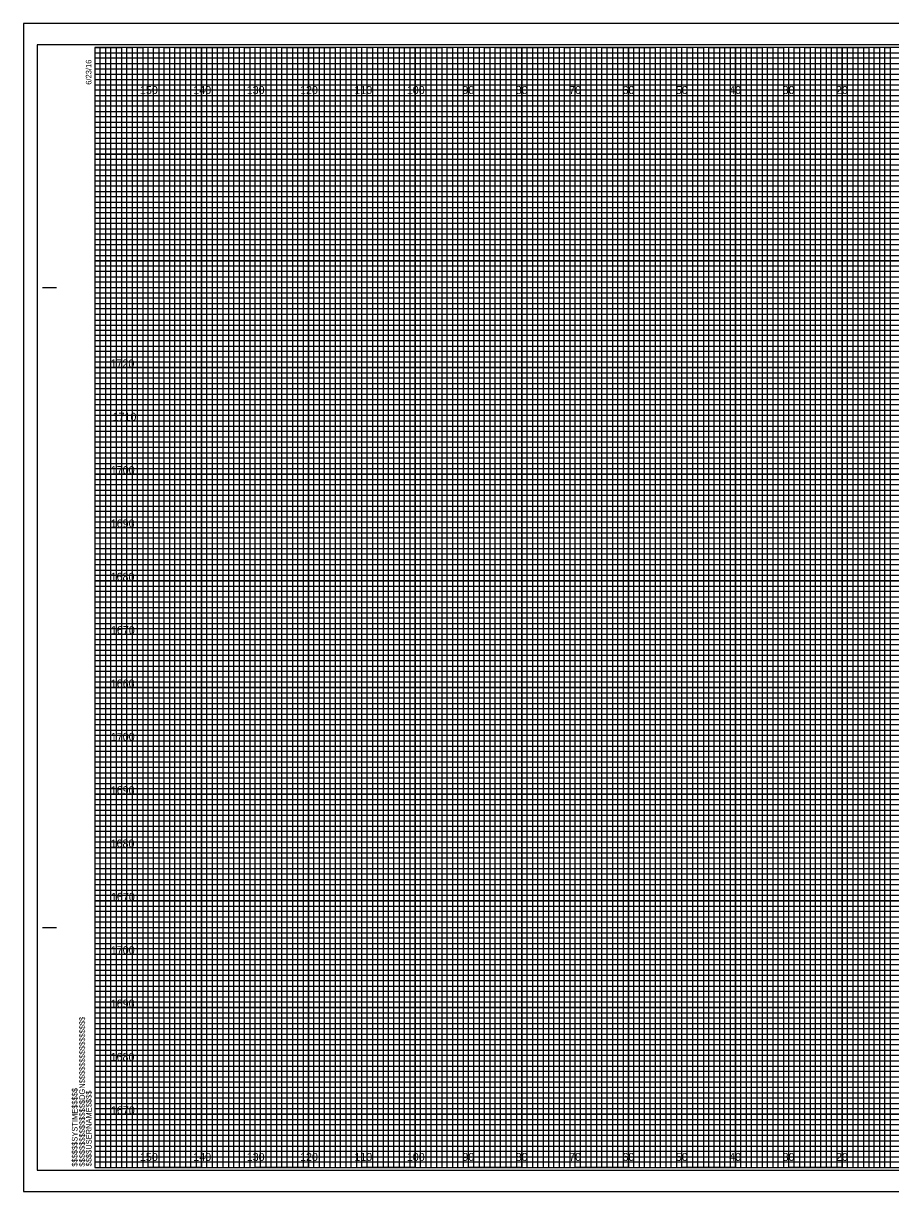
# Model space of a CAD drawing. Extents: x 1443 to 2205, y -29 to 5484.
# Drawn here: x 1443.3 to 1605.8, y -14.8 to 204.2 of the extents above; entities that cross this region are included whole.
import ezdxf

# ---------------------------------------------------------------- set-up
doc = ezdxf.new("R2010")
doc.units = 0
for name, color, linetype in [('Pattern 3', 7, 'Continuous'), ('Prop Retaining Wall', 7, 'Continuous'), ('Prop XS DDE Earthwork Shape', 7, 'Continuous'), ('Prop XS DDE Slope Text', 7, 'Continuous'), ('Prop XS DDE Text', 7, 'Continuous'), ('Prop XS Earthwork Shape', 7, 'Continuous'), ('Prop XS Retaining Wall', 7, 'Continuous'), ('Prop XS Station Labels', 7, 'Continuous'), ('Prop XS Temporary Shoring', 7, 'Continuous'), ('Raster_Level_0', 7, 'Continuous'), ('Scratch_Level_3', 7, 'Continuous')]:
    doc.layers.add(name, color=color, linetype=linetype)

msp = doc.modelspace()

# ---------------------------------------------------------------- linework, layer by layer
at = {"layer": 'Pattern 3'}
for p, q in [((1779.98, 204.21), (1443.28, 204.21)), ((1443.28, 204.21), (1443.28, -14.79)), ((1443.28, -14.79), (1779.98, -14.79))]:
    msp.add_line(p, q, dxfattribs=at)
at = {"layer": 'Prop Retaining Wall'}
for p, q in [((1456.68, 198.71), (1716.68, 198.71)), ((1716.68, 197.69), (1456.68, 197.69)), ((1456.68, 197.69), (1456.68, 196.71)), ((1456.68, 196.71), (1716.68, 196.71)), ((1716.68, 195.6), (1456.68, 195.6)), ((1456.68, 195.6), (1456.68, 193.71)), ((1456.68, 193.71), (1776.68, 193.71))]:
    msp.add_line(p, q, dxfattribs=at)
for points in [[(1456.68, 192.71), (1726.68, 192.71), (1776.68, 192.71), (1776.68, 191.71), (1456.68, 191.71)], [(1456.68, 190.71), (1776.68, 190.71), (1776.68, 188.71), (1456.68, 188.71)], [(1456.68, 187.71), (1776.68, 187.71), (1776.68, 186.71), (1456.68, 186.69)], [(1456.68, 185.71), (1776.68, 185.71), (1776.68, 183.71), (1456.68, 183.71)], [(1456.68, 182.71), (1776.68, 182.71), (1776.68, 181.71), (1456.68, 181.71)], [(1456.68, 180.71), (1776.68, 180.71), (1776.68, 178.71), (1456.68, 178.71)], [(1456.68, 177.71), (1776.68, 177.71), (1776.68, 176.71), (1456.68, 176.71)], [(1456.68, 175.71), (1776.68, 175.71), (1776.68, 173.71), (1456.68, 173.71)], [(1456.68, 172.71), (1776.68, 172.71), (1776.68, 171.71), (1456.68, 171.71)], [(1456.68, 170.71), (1776.68, 170.71), (1776.68, 168.71), (1456.68, 168.71)], [(1456.68, 167.71), (1776.68, 167.71), (1776.68, 166.71), (1456.68, 166.71)], [(1456.68, 165.71), (1776.68, 165.71), (1776.68, 163.66), (1776.68, 162.71), (1776.68, 161.71), (1456.68, 161.71)], [(1456.68, 163.71), (1776.68, 163.71), (1776.68, 162.71), (1456.68, 162.71)], [(1456.68, 160.71), (1776.68, 160.71), (1776.68, 158.71), (1456.68, 158.74)], [(1456.68, 158.74), (1776.68, 158.71), (1776.68, 157.71), (1456.68, 157.71)], [(1456.68, 156.71), (1776.68, 156.71), (1776.68, 155.71), (1456.68, 155.71)], [(1456.68, 153.71), (1776.68, 153.71), (1776.68, 152.71), (1456.68, 152.71)], [(1456.68, 151.71), (1776.68, 151.71), (1776.68, 150.71), (1456.68, 150.71)], [(1456.61, 148.6), (1776.68, 148.6), (1776.68, 147.59), (1456.61, 147.59)], [(1456.68, 146.71), (1776.68, 146.71), (1776.68, 145.71), (1456.68, 145.71)], [(1456.68, 143.71), (1776.68, 143.71), (1776.68, 142.71), (1456.68, 142.71)], [(1456.68, 141.71), (1776.68, 141.71), (1776.68, 140.71), (1456.68, 140.71)], [(1456.68, 138.71), (1776.68, 138.71), (1776.68, 137.71), (1456.68, 137.71)], [(1456.68, 136.71), (1776.68, 136.71), (1776.68, 135.71), (1456.68, 135.71)], [(1456.68, 133.71), (1776.68, 133.71), (1776.68, 132.71), (1456.68, 132.71)], [(1456.68, 131.71), (1776.68, 131.71), (1776.68, 130.71), (1456.68, 130.71)], [(1456.68, 128.71), (1776.68, 128.71), (1776.67, 127.69), (1456.68, 127.71)], [(1456.68, 126.71), (1776.68, 126.71), (1776.68, 125.71), (1456.68, 125.71)], [(1456.68, 123.71), (1776.68, 123.71), (1776.68, 122.71), (1456.68, 122.71)], [(1456.68, 121.71), (1776.68, 121.71), (1776.68, 120.71), (1456.68, 120.71)], [(1456.68, 118.71), (1776.68, 118.71), (1776.68, 117.71), (1456.68, 117.71)], [(1456.68, 116.71), (1776.68, 116.71), (1776.68, 115.71), (1456.68, 115.71)], [(1456.68, 113.71), (1776.68, 113.71), (1776.68, 112.71), (1456.68, 112.71)], [(1456.68, 111.71), (1776.68, 111.71), (1776.68, 110.71), (1456.68, 110.71)], [(1456.68, 108.71), (1776.68, 108.71), (1776.68, 107.71), (1456.68, 107.71)], [(1456.68, 106.7), (1776.75, 106.62), (1776.68, 105.71), (1456.68, 105.71)], [(1456.68, 103.71), (1776.68, 103.71), (1776.68, 102.71), (1456.68, 102.71)], [(1456.68, 101.71), (1776.68, 101.71), (1776.68, 100.71), (1456.68, 100.71)], [(1456.68, 98.71), (1776.68, 98.71), (1776.68, 97.71), (1456.68, 97.71)], [(1456.68, 96.71), (1776.68, 96.71), (1776.68, 95.71), (1456.68, 95.71)], [(1456.68, 93.71), (1776.68, 93.71), (1776.68, 92.71), (1456.68, 92.71)], [(1456.68, 91.71), (1776.68, 91.71), (1776.68, 90.71), (1456.68, 90.71)], [(1456.68, 88.71), (1776.68, 88.71), (1776.68, 87.71), (1456.68, 87.71)], [(1456.68, 86.71), (1776.68, 86.71), (1776.68, 85.71), (1456.68, 85.71)], [(1456.68, 83.71), (1776.68, 83.71), (1776.68, 82.71), (1456.68, 82.71)], [(1456.68, 81.71), (1776.68, 81.71), (1776.68, 80.71), (1456.68, 80.71)], [(1456.68, 78.71), (1776.68, 78.71), (1776.68, 77.71), (1456.68, 77.71)], [(1456.68, 76.71), (1776.68, 76.71), (1776.68, 75.71), (1456.68, 75.71)], [(1456.68, 73.71), (1776.68, 73.71), (1776.68, 72.71), (1456.68, 72.71)], [(1456.68, 71.71), (1776.68, 71.71), (1776.68, 70.71), (1456.68, 70.71)], [(1456.68, 68.71), (1776.68, 68.71), (1776.67, 67.69), (1456.68, 67.71)], [(1456.68, 66.71), (1776.68, 66.71), (1776.68, 65.71), (1456.68, 65.71)], [(1456.68, 63.71), (1776.68, 63.71), (1776.68, 62.71), (1456.68, 62.71)], [(1456.68, 61.71), (1776.68, 61.71), (1776.68, 60.71), (1456.68, 60.71)], [(1456.68, 58.71), (1776.68, 58.71), (1776.68, 57.71), (1456.68, 57.71)], [(1456.68, 56.71), (1776.68, 56.71), (1776.68, 55.71), (1456.68, 55.71)], [(1456.68, 53.71), (1776.68, 53.71), (1776.68, 52.71), (1456.68, 52.71)], [(1456.68, 51.71), (1776.68, 51.71), (1776.68, 50.71), (1456.68, 50.71)], [(1456.68, 48.71), (1776.68, 48.71), (1776.68, 47.71), (1456.68, 47.71)], [(1456.68, 46.7), (1776.75, 46.62), (1776.68, 45.71), (1456.68, 45.71)], [(1456.68, 43.71), (1776.68, 43.71), (1776.68, 42.71), (1456.68, 42.71)], [(1456.68, 41.71), (1776.68, 41.71), (1776.68, 40.71), (1456.68, 40.71)], [(1456.68, 38.71), (1776.68, 38.71), (1776.68, 37.71), (1456.68, 37.71)], [(1456.68, 36.71), (1776.68, 36.71), (1776.68, 35.71), (1456.68, 35.71)], [(1456.68, 33.71), (1776.68, 33.71), (1776.68, 32.71), (1456.68, 32.71)], [(1456.68, 31.71), (1776.68, 31.71), (1776.68, 30.71), (1456.68, 30.71)], [(1456.68, 28.71), (1776.68, 28.71), (1776.68, 27.71), (1456.68, 27.71)], [(1456.68, 26.71), (1776.68, 26.71), (1776.68, 25.71), (1456.68, 25.71)], [(1456.68, 23.71), (1776.68, 23.71), (1776.68, 22.71), (1456.68, 22.71)], [(1456.68, 21.71), (1776.68, 21.71), (1776.68, 20.71), (1456.68, 20.71)], [(1456.68, 18.71), (1776.68, 18.71), (1776.68, 17.71), (1456.68, 17.71)], [(1456.68, 16.71), (1776.68, 16.71), (1776.68, 15.71), (1456.68, 15.71)], [(1456.68, 13.71), (1776.68, 13.71), (1776.68, 12.71), (1456.68, 12.71)], [(1456.68, 11.71), (1776.68, 11.71), (1776.68, 10.71), (1456.68, 10.71)], [(1456.68, 8.71), (1776.68, 8.71), (1776.68, 7.71), (1456.68, 7.71)], [(1456.68, 6.71), (1776.68, 6.71), (1776.68, 5.71), (1456.68, 5.71)], [(1456.68, 3.71), (1776.68, 3.71), (1776.68, 2.71), (1456.68, 2.71)], [(1456.68, 1.71), (1776.68, 1.71), (1776.68, 0.71), (1456.68, 0.71)], [(1456.68, -1.29), (1776.68, -1.29), (1776.68, -2.29), (1456.68, -2.29)], [(1456.68, -3.29), (1776.68, -3.29), (1776.68, -4.29), (1456.68, -4.29)], [(1456.68, -6.29), (1776.68, -6.29), (1776.68, -7.29), (1456.68, -7.29)], [(1456.68, -8.29), (1776.68, -8.29), (1776.68, -9.29), (1456.68, -9.29)]]:
    msp.add_lwpolyline(points, dxfattribs=at)
at = {"layer": 'Prop XS DDE Earthwork Shape'}
msp.add_lwpolyline([(1445.88, -10.79), (1779.08, -10.79), (1779.08, 200.21), (1445.88, 200.21)], close=True, dxfattribs=at)
at = {"layer": 'Prop XS DDE Slope Text'}
for points in [[(1456.68, -10.29), (1457.68, -10.29), (1457.68, 199.71), (1458.68, 199.71), (1458.68, -10.29)], [(1458.68, -10.29), (1459.68, -10.29), (1459.68, 199.71), (1460.68, 199.71), (1460.68, -10.29)], [(1461.68, -10.29), (1462.68, -10.29), (1462.68, 199.71), (1463.68, 199.71), (1463.68, -10.29)], [(1463.68, -10.29), (1464.68, -10.29), (1464.68, 199.71), (1465.68, 199.71), (1465.68, -10.29)], [(1466.68, -10.29), (1467.68, -10.29), (1467.68, 199.71), (1468.68, 199.71), (1468.68, -10.29)], [(1468.68, -10.29), (1469.68, -10.29), (1469.68, 199.71), (1470.68, 199.71), (1470.68, -10.29)], [(1471.68, -10.29), (1472.68, -10.29), (1472.68, 199.71), (1473.68, 199.71), (1473.68, -10.29)], [(1473.68, -10.29), (1474.68, -10.29), (1474.68, 199.71), (1475.68, 199.71), (1475.68, -10.29)], [(1476.68, -10.29), (1477.68, -10.29), (1477.68, 199.71), (1478.68, 199.71), (1478.68, -10.29)], [(1478.68, -10.29), (1479.68, -10.29), (1479.68, 199.71), (1480.68, 199.71), (1480.68, -10.29)], [(1481.68, -10.29), (1482.68, -10.29), (1482.68, 199.71), (1483.68, 199.71), (1483.68, -10.29)], [(1483.68, -10.29), (1484.68, -10.29), (1484.68, 199.71), (1485.68, 199.71), (1485.68, -10.29)], [(1486.68, -10.29), (1487.68, -10.29), (1487.68, 199.71), (1488.68, 199.71), (1488.68, -10.29)], [(1488.68, -10.29), (1489.68, -10.29), (1489.68, 199.71), (1490.68, 199.71), (1490.68, -10.29)], [(1491.68, -10.29), (1492.68, -10.29), (1492.68, 199.71), (1493.68, 199.71), (1493.68, -10.29)], [(1493.68, -10.29), (1494.68, -10.29), (1494.68, 199.71), (1495.68, 199.71), (1495.68, -10.29)], [(1496.68, -10.29), (1497.68, -10.29), (1497.68, 199.71), (1498.68, 199.71), (1498.68, -10.29)], [(1498.68, -10.29), (1499.68, -10.29), (1499.68, 199.71), (1500.68, 199.71), (1500.68, -10.29)], [(1501.68, -10.29), (1502.68, -10.29), (1502.68, 199.71), (1503.68, 199.71), (1503.68, -10.29)], [(1503.68, -10.29), (1504.68, -10.29), (1504.68, 199.71), (1505.68, 199.71), (1505.68, -10.29)], [(1506.68, -10.29), (1507.68, -10.29), (1507.68, 199.71), (1508.68, 199.71), (1508.68, -10.29)], [(1508.68, -10.29), (1509.68, -10.29), (1509.68, 199.71), (1510.68, 199.71), (1510.68, -10.29)], [(1511.68, -10.29), (1512.68, -10.29), (1512.68, 199.71), (1513.68, 199.71), (1513.68, -10.29)], [(1513.68, -10.29), (1514.68, -10.29), (1514.68, 199.71), (1515.68, 199.71), (1515.68, -10.29)], [(1516.68, -10.29), (1517.68, -10.29), (1517.68, 199.71), (1518.68, 199.71), (1518.68, -10.29)], [(1518.68, -10.29), (1519.68, -10.29), (1519.68, 199.71), (1520.68, 199.71), (1520.68, -10.29)], [(1521.68, -10.29), (1522.68, -10.29), (1522.68, 199.71), (1523.68, 199.71), (1523.68, -10.29)], [(1523.68, -10.29), (1524.68, -10.29), (1524.68, 199.71), (1525.68, 199.71), (1525.68, -10.29)], [(1526.68, -10.29), (1527.68, -10.29), (1527.68, 199.71), (1528.68, 199.71), (1528.68, -10.29)], [(1528.68, -10.29), (1529.68, -10.29), (1529.68, 199.71), (1530.68, 199.71), (1530.68, -10.29)], [(1531.68, -10.29), (1532.68, -10.29), (1532.68, 199.71), (1533.68, 199.71), (1533.68, -10.29)], [(1533.68, -10.29), (1534.68, -10.29), (1534.68, 199.71), (1535.68, 199.71), (1535.68, -10.29)], [(1536.68, -10.29), (1537.68, -10.29), (1537.68, 199.71), (1538.68, 199.71), (1538.68, -10.29)], [(1538.68, -10.29), (1539.68, -10.29), (1539.68, 199.71), (1540.68, 199.71), (1540.68, -10.29)], [(1541.68, -10.29), (1542.68, -10.29), (1542.68, 199.71), (1543.68, 199.71), (1543.68, -10.29)], [(1543.68, -10.29), (1544.68, -10.29), (1544.68, 199.71), (1545.68, 199.71), (1545.68, -10.29)], [(1546.68, -10.29), (1547.68, -10.29), (1547.68, 199.71), (1548.68, 199.71), (1548.68, -10.29)], [(1548.68, -10.29), (1549.68, -10.29), (1549.68, 199.71), (1550.68, 199.71), (1550.68, -10.29)], [(1551.68, -10.29), (1552.68, -10.29), (1552.68, 199.71), (1553.68, 199.71), (1553.68, -10.29)], [(1553.68, -10.29), (1554.68, -10.29), (1554.68, 199.71), (1555.68, 199.71), (1555.68, -10.29)], [(1556.68, -10.29), (1557.68, -10.29), (1557.68, 199.71), (1558.68, 199.71), (1558.68, -10.29)], [(1558.68, -10.29), (1559.68, -10.29), (1559.68, 199.71), (1560.68, 199.71), (1560.68, -10.29)], [(1561.68, -10.29), (1562.68, -10.29), (1562.68, 199.71), (1563.68, 199.71), (1563.68, -10.29)], [(1563.68, -10.29), (1564.68, -10.29), (1564.68, 199.71), (1565.68, 199.71), (1565.68, -10.29)], [(1566.68, -10.29), (1567.68, -10.29), (1567.68, 199.71), (1568.68, 199.71), (1568.68, -10.29)], [(1568.68, -10.29), (1569.68, -10.29), (1569.68, 199.71), (1570.68, 199.71), (1570.68, -10.29)], [(1571.68, -10.29), (1572.68, -10.29), (1572.68, 199.71), (1573.68, 199.71), (1573.68, -10.29)], [(1573.68, -10.29), (1574.68, -10.29), (1574.68, 199.71), (1575.68, 199.71), (1575.68, -10.29)], [(1576.68, -10.29), (1577.68, -10.29), (1577.68, 199.71), (1578.68, 199.71), (1578.68, -10.29)], [(1578.68, -10.29), (1579.68, -10.29), (1579.68, 199.71), (1580.68, 199.71), (1580.68, -10.29)], [(1581.68, -10.29), (1582.68, -10.29), (1582.68, 199.71), (1583.68, 199.71), (1583.68, -10.29)], [(1583.68, -10.29), (1584.68, -10.29), (1584.68, 199.71), (1585.68, 199.71), (1585.68, -10.29)], [(1586.68, -10.29), (1587.68, -10.29), (1587.68, 199.71), (1588.68, 199.71), (1588.68, -10.29)], [(1588.68, -10.29), (1589.68, -10.29), (1589.68, 199.71), (1590.68, 199.71), (1590.68, -10.29)], [(1591.68, -10.29), (1592.68, -10.29), (1592.68, 199.71), (1593.68, 199.71), (1593.68, -10.29)], [(1593.68, -10.29), (1594.68, -10.29), (1594.68, 199.71), (1595.68, 199.71), (1595.68, -10.29)], [(1596.68, -10.29), (1597.68, -10.29), (1597.68, 199.71), (1598.68, 199.71), (1598.68, -10.29)], [(1598.68, -10.29), (1599.68, -10.29), (1599.68, 199.71), (1600.68, 199.71), (1600.68, -10.29)], [(1601.68, -10.29), (1602.68, -10.29), (1602.68, 199.71), (1603.68, 199.71), (1603.68, -10.29)], [(1603.68, -10.29), (1604.68, -10.29), (1604.68, 199.71), (1605.68, 199.71), (1605.68, -10.29)]]:
    msp.add_lwpolyline(points, dxfattribs=at)
at = {"layer": 'Prop XS DDE Text'}
msp.add_lwpolyline([(1443.28, -14.79), (1779.98, -14.79), (1779.98, 204.21), (1443.28, 204.21)], close=True, dxfattribs=at)
at = {"layer": 'Prop XS Earthwork Shape'}
for p, q in [((1466.68, 199.71), (1456.68, 199.71)), ((1466.68, -10.29), (1466.68, 199.71)), ((1486.68, 199.71), (1476.68, 199.71)), ((1476.68, 199.71), (1476.68, -10.29)), ((1486.68, -10.29), (1486.68, 199.71)), ((1506.68, 199.71), (1496.68, 199.71)), ((1496.68, 199.71), (1496.68, -10.29)), ((1506.68, -10.29), (1506.68, 199.71)), ((1526.68, 199.71), (1516.68, 199.71)), ((1516.68, 199.71), (1516.68, -10.29)), ((1526.68, -10.29), (1526.68, 199.71)), ((1546.68, 199.71), (1536.68, 199.71)), ((1536.68, 199.71), (1536.68, -10.29)), ((1546.68, -10.29), (1546.68, 199.71)), ((1566.68, 199.71), (1556.68, 199.71)), ((1556.68, 199.71), (1556.68, -10.29)), ((1566.68, -10.29), (1566.68, 199.71)), ((1586.68, 199.71), (1576.68, 199.71)), ((1576.68, 199.71), (1576.68, -10.29)), ((1586.68, -10.29), (1586.68, 199.71)), ((1606.68, 199.71), (1596.68, 199.71)), ((1596.68, 199.71), (1596.68, -10.29)), ((1476.68, -10.29), (1466.68, -10.29)), ((1496.68, -10.29), (1486.68, -10.29)), ((1516.68, -10.29), (1506.68, -10.29)), ((1536.68, -10.29), (1526.68, -10.29)), ((1556.68, -10.29), (1546.68, -10.29)), ((1576.68, -10.29), (1566.68, -10.29)), ((1596.68, -10.29), (1586.68, -10.29))]:
    msp.add_line(p, q, dxfattribs=at)
for points in [[(1456.68, 189.71), (1776.68, 189.71), (1776.68, 179.71), (1456.68, 179.71)], [(1456.68, 169.71), (1776.68, 169.71), (1776.68, 159.71), (1456.68, 159.71)], [(1456.68, 149.71), (1776.68, 149.71), (1776.68, 139.71), (1456.68, 139.71)], [(1456.68, 129.71), (1776.68, 129.71), (1776.68, 119.71), (1456.68, 119.71)], [(1456.68, 109.71), (1776.68, 109.71), (1776.68, 99.71), (1456.68, 99.71)], [(1456.68, 89.71), (1776.68, 89.71), (1776.68, 79.71), (1456.68, 79.71)], [(1456.68, 69.71), (1776.68, 69.71), (1776.68, 59.71), (1456.68, 59.71)], [(1456.68, 49.71), (1776.68, 49.71), (1776.68, 39.71), (1456.68, 39.71)], [(1456.68, 29.71), (1776.68, 29.71), (1776.68, 19.71), (1456.68, 19.71)], [(1456.68, 9.71), (1776.68, 9.71), (1776.68, -0.29), (1456.68, -0.29)]]:
    msp.add_lwpolyline(points, dxfattribs=at)
at = {"layer": 'Prop XS Retaining Wall'}
for p, q in [((1446.88, 154.71), (1449.38, 154.71)), ((1446.98, 154.71), (1449.48, 154.71)), ((1446.88, 34.71), (1449.38, 34.71)), ((1446.98, 34.71), (1449.48, 34.71)), ((1456.68, -10.29), (1456.68, -10.29)), ((1456.68, -10.29), (1456.68, -10.29)), ((1456.68, -10.29), (1456.68, -10.29)), ((1456.68, -10.29), (1456.68, -10.29)), ((1456.68, -10.29), (1456.68, -10.29)), ((1456.68, -10.29), (1456.68, -10.29)), ((1456.68, -10.29), (1456.68, -10.29))]:
    msp.add_line(p, q, dxfattribs=at)
msp.add_lwpolyline([(1776.68, 199.71), (1456.68, 199.71), (1456.68, -10.29), (1776.68, -10.29)], close=True, dxfattribs=at)
at = {"layer": 'Prop XS Station Labels'}
for points in [[(1456.68, 199.71), (1461.68, 199.71), (1461.68, -10.29), (1471.68, -10.29), (1471.68, 199.71), (1481.68, 199.71), (1481.68, -10.29), (1491.68, -10.29), (1491.68, 199.71), (1501.68, 199.71), (1501.68, -10.29), (1511.68, -10.29), (1511.68, 199.71), (1521.68, 199.71), (1521.68, -10.29), (1531.68, -10.29), (1531.68, 199.71), (1541.68, 199.71), (1541.68, -10.29), (1551.68, -10.29), (1551.68, 199.71), (1561.68, 199.71), (1561.68, -10.29), (1571.68, -10.29), (1571.68, 199.71), (1581.68, 199.71), (1581.68, -10.29), (1591.68, -10.29), (1591.68, 199.71), (1601.68, 199.71), (1601.68, -10.29), (1611.68, -10.29)], [(1456.68, 194.71), (1731.68, 194.71)], [(1456.68, 174.71), (1776.68, 174.71), (1776.68, 184.71), (1456.68, 184.71)], [(1456.68, 154.71), (1776.68, 154.71), (1776.68, 164.71), (1456.68, 164.71)], [(1456.68, 134.71), (1776.68, 134.71), (1776.68, 144.71), (1456.68, 144.71)], [(1456.68, 114.71), (1776.68, 114.71), (1776.68, 124.71), (1456.68, 124.71)], [(1456.68, 94.71), (1776.68, 94.71), (1776.68, 104.71), (1456.68, 104.71)], [(1456.68, 74.71), (1776.68, 74.71), (1776.68, 84.71), (1456.68, 84.71)], [(1456.68, 54.71), (1776.68, 54.71), (1776.68, 64.71), (1456.68, 64.71)], [(1456.68, 34.71), (1776.68, 34.71), (1776.68, 44.71), (1456.68, 44.71)], [(1456.68, 14.71), (1776.68, 14.71), (1776.68, 24.71), (1456.68, 24.71)], [(1456.68, -5.29), (1776.68, -5.29), (1776.68, 4.71), (1456.68, 4.71)]]:
    msp.add_lwpolyline(points, dxfattribs=at)
at = {"layer": 'Prop XS Temporary Shoring'}
for p, q in [((1466.68, -10.29), (1466.68, 199.71)), ((1476.68, -10.29), (1476.68, 199.71)), ((1486.68, -10.29), (1486.68, 199.71)), ((1496.68, -10.29), (1496.68, 199.71)), ((1506.68, -10.29), (1506.68, 199.71)), ((1516.68, -10.29), (1516.68, 199.71)), ((1526.68, -10.29), (1526.68, 199.71)), ((1536.68, -10.29), (1536.68, 199.71)), ((1546.68, -10.29), (1546.68, 199.71)), ((1556.68, -10.29), (1556.68, 199.71)), ((1566.68, -10.29), (1566.68, 199.71)), ((1576.68, -10.29), (1576.68, 199.71)), ((1586.68, -10.29), (1586.68, 199.71)), ((1596.68, -10.29), (1596.68, 199.71)), ((1456.68, 189.71), (1776.68, 189.71)), ((1456.68, 179.71), (1776.68, 179.71)), ((1456.68, 169.71), (1776.68, 169.71)), ((1456.68, 159.71), (1776.68, 159.71)), ((1456.68, 149.71), (1776.68, 149.71)), ((1456.68, 139.71), (1776.68, 139.71)), ((1456.68, 129.71), (1776.68, 129.71)), ((1456.68, 119.71), (1776.68, 119.71)), ((1456.68, 109.71), (1776.68, 109.71)), ((1456.68, 99.71), (1776.68, 99.71)), ((1456.68, 89.71), (1776.68, 89.71)), ((1456.68, 79.71), (1776.68, 79.71)), ((1456.68, 69.71), (1776.68, 69.71)), ((1456.68, 59.71), (1776.68, 59.71)), ((1456.68, 49.71), (1776.68, 49.71)), ((1456.68, 39.71), (1776.68, 39.71)), ((1456.68, 29.71), (1776.68, 29.71)), ((1456.68, 19.71), (1776.68, 19.71)), ((1456.68, 9.71), (1776.68, 9.71)), ((1456.68, -0.29), (1776.68, -0.29))]:
    msp.add_line(p, q, dxfattribs=at)

# ---------------------------------------------------------------- texts
at = {"layer": 'Prop XS Retaining Wall'}
for s, p in [('6/23/16', (1456.03, 192.71)), ('$$$$$$$$$$$$$$$$DGN$$$$$$$$$$$$$$$$', (1454.8, -10.11)), ('$$$$$$SYSTIME$$$$$', (1453.42, -10.11)), ('$$$$USERNAME$$$$', (1456.06, -10.06))]:
    msp.add_text(s, height=1.05, rotation=90, dxfattribs=at).set_placement(p)
at = {"layer": 'Raster_Level_0'}
for s, p in [('150', (1465.12, 190.96)), ('140', (1475.12, 190.96)), ('130', (1485.12, 190.96)), ('120', (1495.12, 190.96)), ('110', (1505.3, 190.96)), ('100', (1515.12, 190.96)), ('90', (1525.53, 190.96)), ('80', (1535.53, 190.96)), ('70', (1545.53, 190.96)), ('60', (1555.53, 190.96)), ('50', (1565.53, 190.96)), ('40', (1575.53, 190.96)), ('30', (1585.53, 190.96)), ('20', (1595.53, 190.96)), ('150', (1465.12, -9.04)), ('140', (1475.12, -9.04)), ('130', (1485.12, -9.04)), ('120', (1495.12, -9.04)), ('110', (1505.3, -9.04)), ('100', (1515.12, -9.04)), ('90', (1525.53, -9.04)), ('80', (1535.53, -9.04)), ('70', (1545.53, -9.04)), ('60', (1555.53, -9.04)), ('50', (1565.53, -9.04)), ('40', (1575.53, -9.04)), ('30', (1585.53, -9.04)), ('20', (1595.53, -9.04))]:
    msp.add_text(s, height=1.5, dxfattribs=at).set_placement(p)
at = {"layer": 'Scratch_Level_3'}
for s, p in [('1720', (1459.61, 139.71)), ('1710', (1459.99, 129.71)), ('1700', (1459.66, 119.71)), ('1690', (1459.65, 109.71)), ('1680', (1459.62, 99.71)), ('1670', (1459.68, 89.71)), ('1660', (1459.65, 79.71)), ('1700', (1459.66, 69.71)), ('1690', (1459.65, 59.71)), ('1680', (1459.62, 49.71)), ('1670', (1459.68, 39.71)), ('1700', (1459.66, 29.71)), ('1690', (1459.65, 19.71)), ('1680', (1459.62, 9.71)), ('1670', (1459.68, -0.29))]:
    msp.add_text(s, height=1.5, dxfattribs=at).set_placement(p)

doc.saveas('drawing.dxf')
